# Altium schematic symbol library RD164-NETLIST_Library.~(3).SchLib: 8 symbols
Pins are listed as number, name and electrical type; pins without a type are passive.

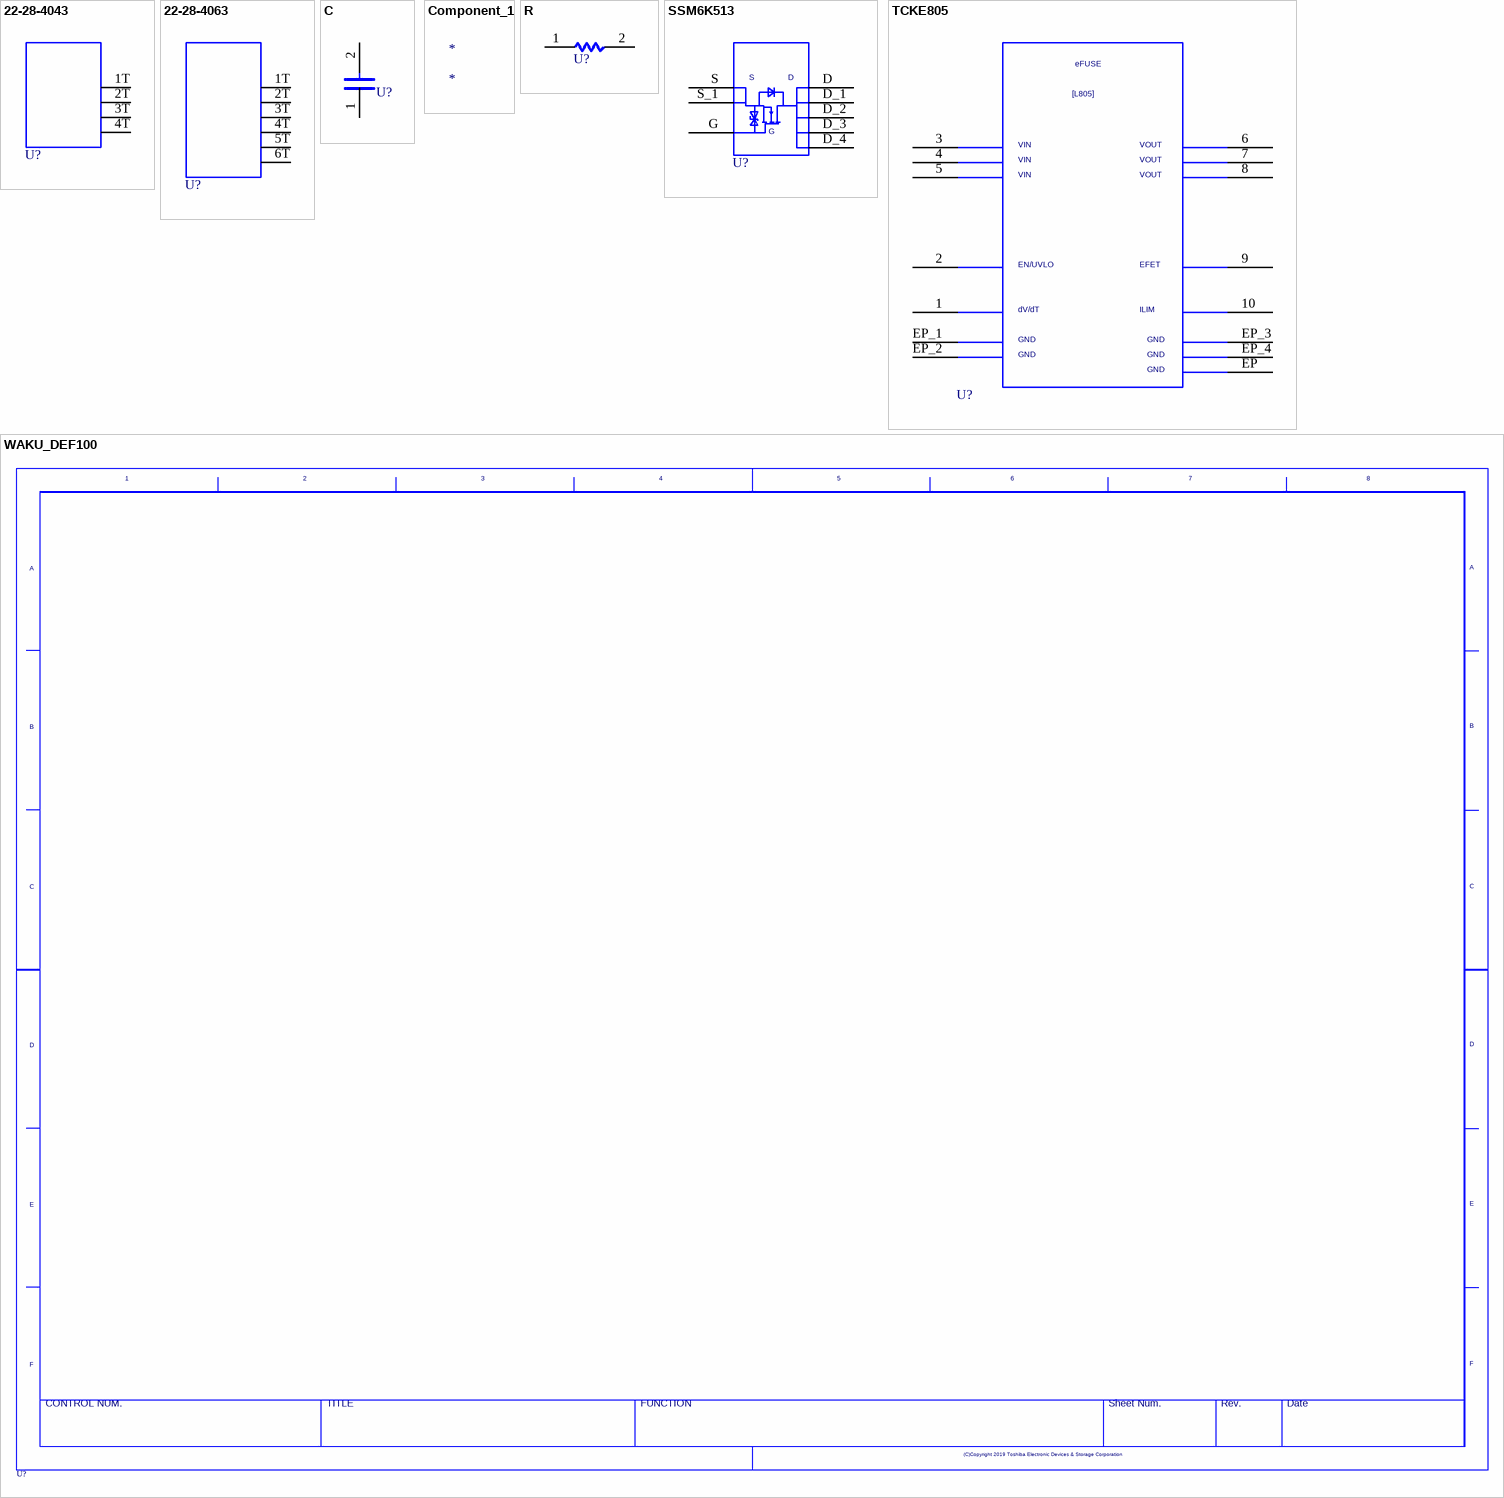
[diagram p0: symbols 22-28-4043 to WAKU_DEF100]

## 22-28-4043
designator U?  (value not drawn)
SAVEAREA0: -8829,-843,28769,23958; SAVECOUNT: 23; TIME: 13:28:28; UPDATEUSER: cae; UPDATETIME: 15:59:12; OriginalSymbolOrigin: (2540,20320); Altium-Right: 50; Altium-Bottom: 70
pins: 1T, 2T, 3T, 4T

## 22-28-4063
designator U?  (value not drawn)
SAVEAREA0: -13107,-601,32466,29460; SAVECOUNT: 23; TIME: 13:28:28; UPDATEUSER: cae; UPDATETIME: 16:00:22; OriginalSymbolOrigin: (2540,25400); Altium-Right: 50; Altium-Bottom: 90
pins: 1T, 2T, 3T, 4T, 5T, 6T

## C
designator U?  (value not drawn)
OriginalSymbolOrigin: (2540,7620); Altium-Right: 20; Altium-Bottom: 10
pins: 1, 2

## Component_1
designator *

## R
designator U?  (value not drawn)
OriginalSymbolOrigin: (5080,5080); Altium-Right: 20
pins: 1, 2

## SSM6K513
designator U?  (value not drawn)
SAVEAREA0: -9081,-242,36640,23504; TIME: 18:57:44; UPDATEUSER: cae; UPDATETIME: 16:12:40; SAVECOUNT: 16; OriginalSymbolOrigin: (7620,20320); Altium-Right: 50; Altium-Bottom: 80
pins: D, D_1, D_2, D_3, D_4, G, S, S_1

## TCKE805
designator U?  (value not drawn)
SAVEAREA0: -21400,-662,82488,64135; SAVECOUNT: 22; TIME: 17:55:46; UPDATEUSER: cae; UPDATETIME: 15:44:05; OriginalSymbolOrigin: (7620,60960); Altium-Right: 180; Altium-Bottom: 230
pins: 1, 2, 3, 4, 5, 6, 7, 8, 9, 10, EP, EP_1, EP_2, EP_3, EP_4

## WAKU_DEF100
designator U?  (value not drawn)
PLOTTIME: HH:MM; SAVEAREA0: 198008,-65938,436964,90161; TIME: 14:30:25; UPDATEUSER: d5009410; UPDATETIME: 15:37:05; SAVECOUNT: 4; OriginalSymbolOrigin: (10160,284480); Altium-Right: 1570; Altium-Bottom: 1070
